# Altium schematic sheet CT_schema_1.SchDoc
size 611 x 441 mm
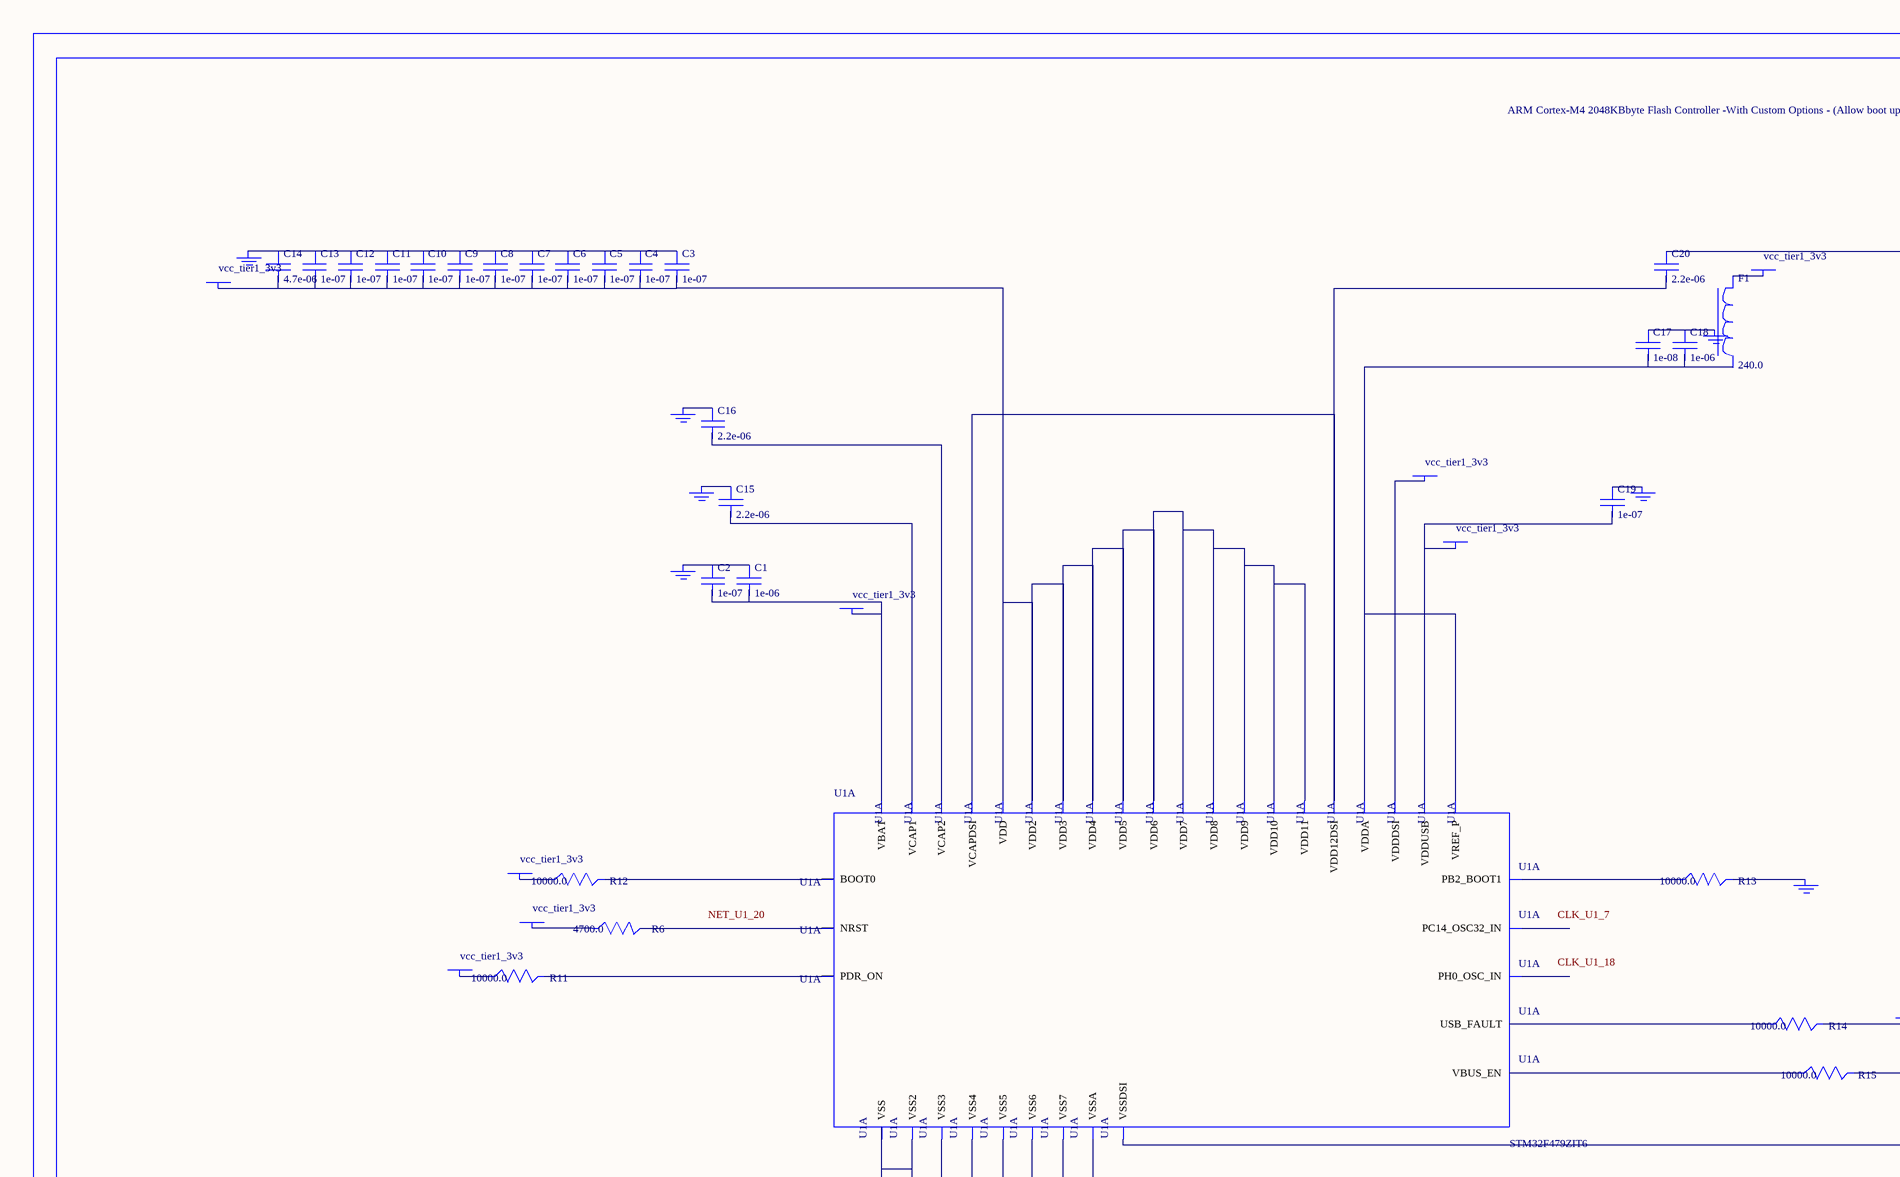
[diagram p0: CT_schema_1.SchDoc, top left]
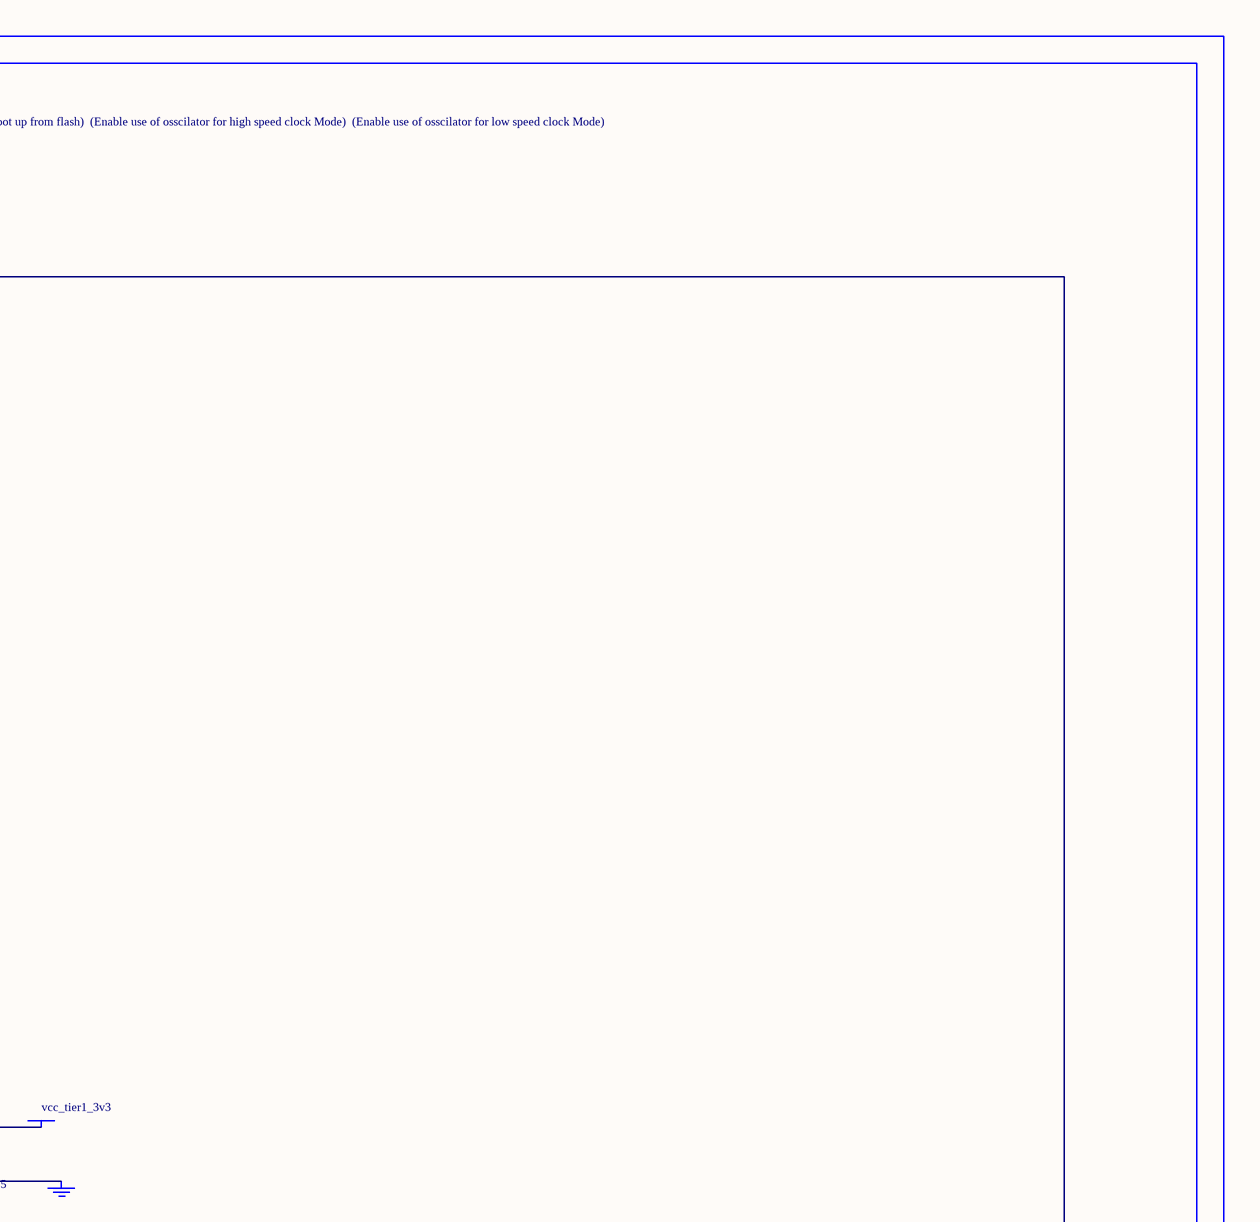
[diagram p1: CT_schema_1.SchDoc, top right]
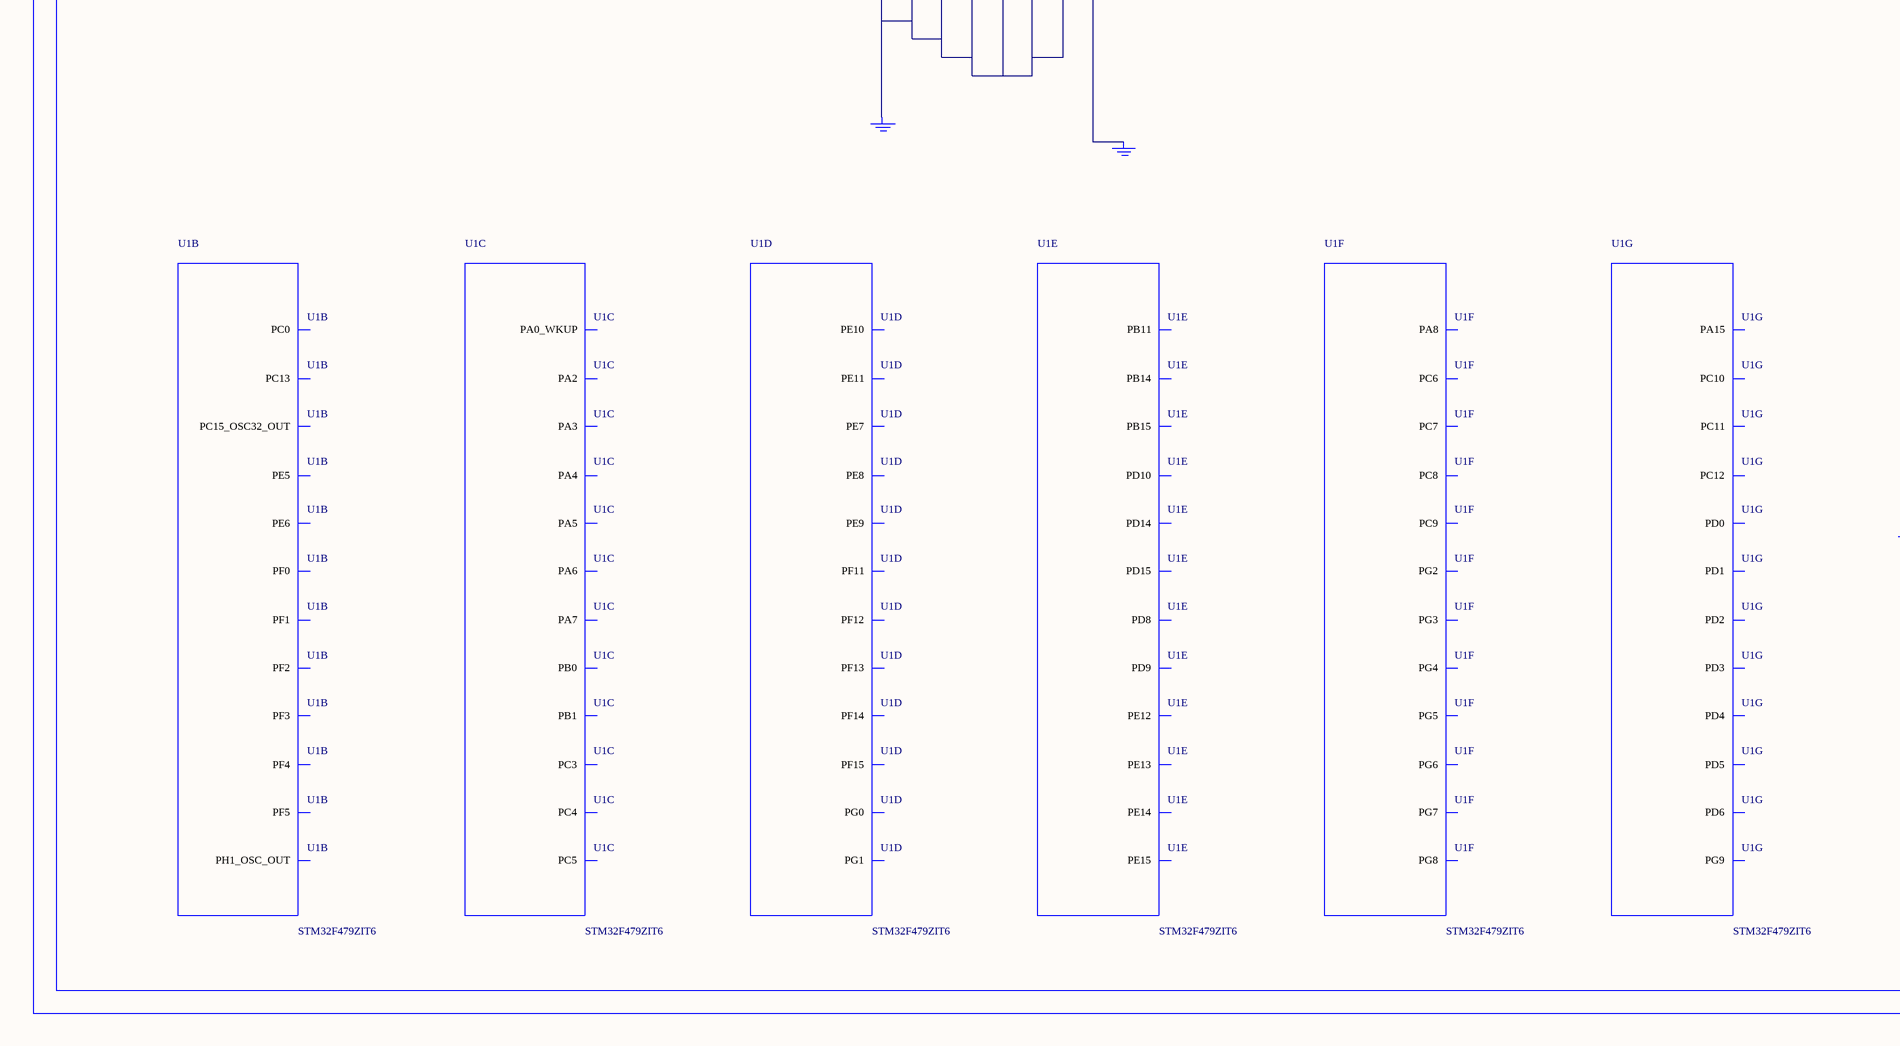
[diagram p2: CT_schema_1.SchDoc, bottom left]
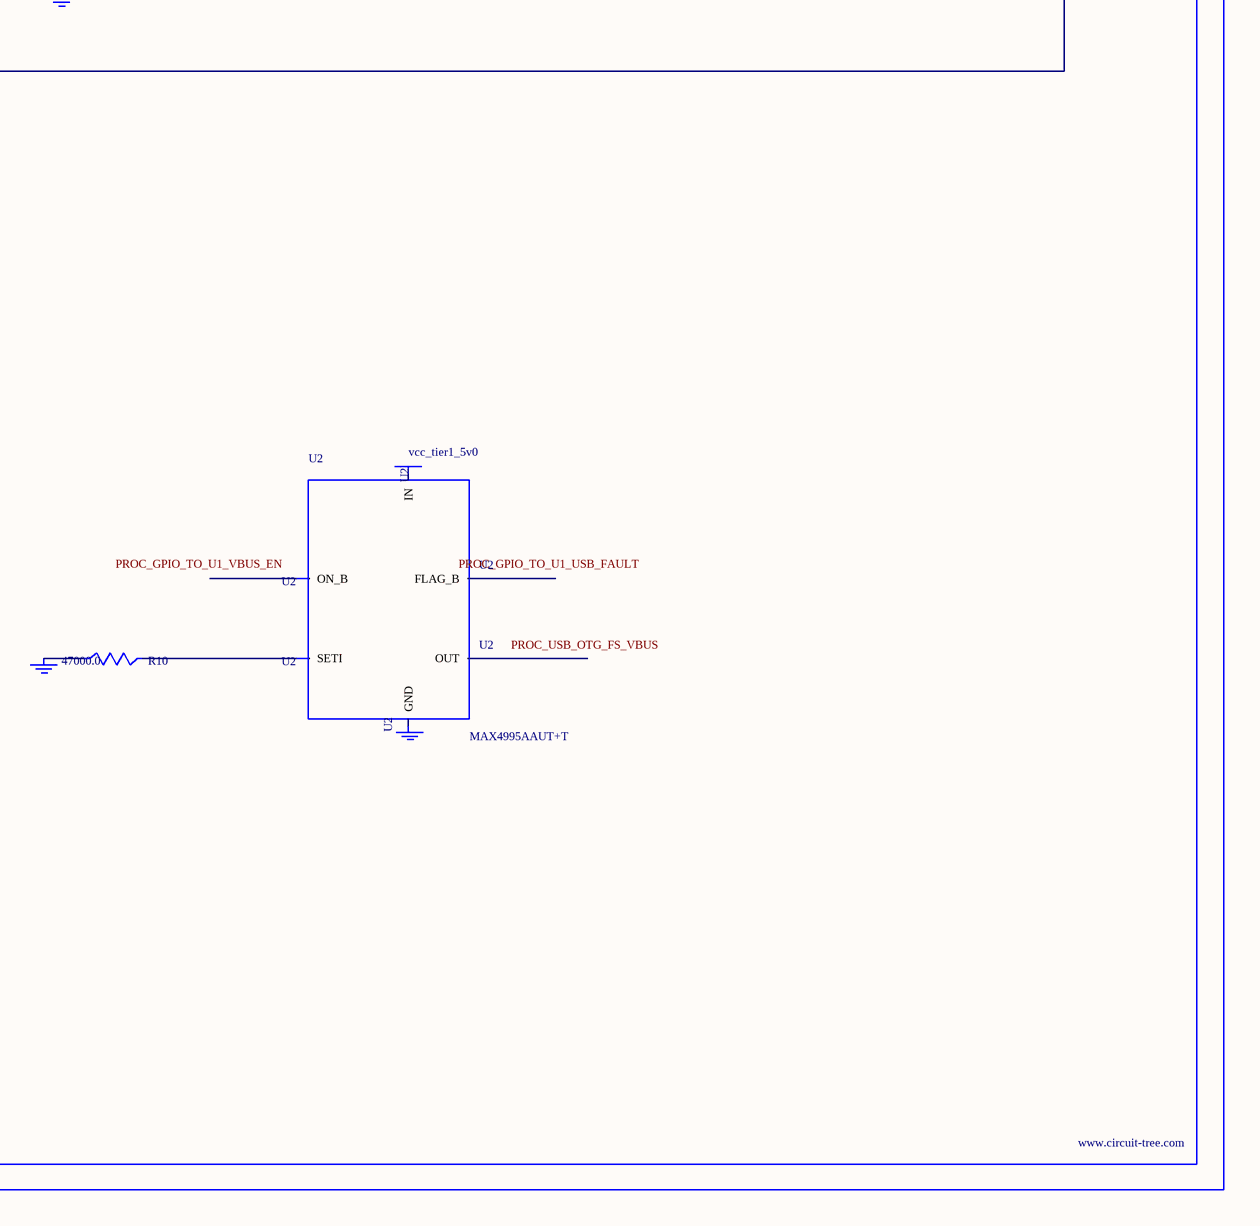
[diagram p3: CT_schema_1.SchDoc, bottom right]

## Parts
BORDER0  (no value)
C1  1e-06  [C0603]
C2  1e-07  [C0603]
C3  1e-07  [C0603]
C4  1e-07  [C0603]
C5  1e-07  [C0603]
C6  1e-07  [C0603]
C7  1e-07  [C0603]
C8  1e-07  [C0603]
C9  1e-07  [C0603]
C10  1e-07  [C0603]
C11  1e-07  [C0603]
C12  1e-07  [C0603]
C13  1e-07  [C0603]
C14  4.7e-06  [C0603]
C15  2.2e-06  [C0603]
C16  2.2e-06  [C0603]
C17  1e-08  [C0603]
C18  1e-06  [C0603]
C19  1e-07  [C0603]
C20  2.2e-06  [C0603]
F1  240.0  [L0603]
GND_INSTANCE_0_0  (no value)
GND_INSTANCE_0_1  (no value)
GND_INSTANCE_0_2  (no value)
GND_INSTANCE_0_3  (no value)
GND_INSTANCE_0_4  (no value)
GND_INSTANCE_0_5  (no value)
GND_INSTANCE_0_6  (no value)
GND_INSTANCE_0_7  (no value)
GND_INSTANCE_0_8  (no value)
GND_INSTANCE_0_9  (no value)
GND_INSTANCE_0_10  (no value)
GND_INSTANCE_0_11  (no value)
POWER_INSTANCE_0_0  vcc_tier1_3v3
POWER_INSTANCE_0_1  vcc_tier1_3v3
POWER_INSTANCE_0_2  vcc_tier1_3v3
POWER_INSTANCE_0_3  vcc_tier1_3v3
POWER_INSTANCE_0_4  vcc_tier1_3v3
POWER_INSTANCE_0_5  vcc_tier1_3v3
POWER_INSTANCE_0_6  vcc_tier1_3v3
POWER_INSTANCE_0_7  vcc_tier1_3v3
POWER_INSTANCE_0_8  vcc_tier1_3v3
POWER_INSTANCE_0_9  vcc_tier1_5v0
R6  4700.0  [R0603]
R10  47000.0  [R0603]
R11  10000.0  [R0603]
R12  10000.0  [R0603]
R13  10000.0  [R0603]
R14  10000.0  [R0603]
R15  10000.0  [R0603]
U1  STM32F479ZIT6  [LQFP144]  (parts A,B,C,D,E,F,G of 13)
U2  MAX4995AAUT+T  [SOT-23-6]

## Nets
NetC1_1: C1.1 C2.1 GND_INSTANCE_0_1.0(GND)
NetC1_2: C1.2 C2.2 POWER_INSTANCE_0_1.0(PWR) U1.5(VBAT)
NetC3_1: C3.1 C4.1 C5.1 C6.1 C7.1 C8.1 C9.1 C10.1 C11.1 C12.1 C13.1 C14.1 GND_INSTANCE_0_2.0(GND)
NetC3_2: C3.2 C4.2 C5.2 C6.2 C7.2 C8.2 C9.2 C10.2 C11.2 C12.2 C13.2 C14.2 POWER_INSTANCE_0_2.0(PWR) U1.16(VDD) U1.25(VDD2) U1.34(VDD3) U1.46(VDD4) U1.56(VDD5) U1.66(VDD6) U1.77(VDD7) U1.110(VDD8) U1.123(VDD9) U1.130(VDD10) U1.143(VDD11)
NetC15_1: C15.1 GND_INSTANCE_0_6.0(GND)
NetC15_2: C15.2 U1.65(VCAP1)
NetC16_1: C16.1 GND_INSTANCE_0_8.0(GND)
NetC16_2: C16.2 U1.108(VCAP2)
NetC17_1: C17.1 C18.1 GND_INSTANCE_0_4.0(GND)
NetC17_2: C17.2 C18.2 U1.27(VREF_P) U1.28(VDDA)
NetC19_1: C19.1 GND_INSTANCE_0_7.0(GND)
NetC19_2: C19.2 POWER_INSTANCE_0_5.0(PWR) U1.97(VDDUSB)
NetC20_1: C20.1 U1.84(VSSDSI)
NetC20_2: C20.2 U1.81(VCAPDSI) U1.87(VDD12DSI)
NetF1_1: F1.1 POWER_INSTANCE_0_3.0(PWR)
NetGND_INSTANCE_0_0_0: GND_INSTANCE_0_0.0(GND) R15.2
NetGND_INSTANCE_0_3_0: GND_INSTANCE_0_3.0(GND) U1.26(VSSA)
NetGND_INSTANCE_0_5_0: GND_INSTANCE_0_5.0(GND) R13.2
NetGND_INSTANCE_0_9_0: GND_INSTANCE_0_9.0(GND) U1.15(VSS) U1.33(VSS2) U1.55(VSS3) U1.76(VSS4) U1.109(VSS5) U1.122(VSS6) U1.129(VSS7)
NetGND_INSTANCE_0_10_0: GND_INSTANCE_0_10.0(GND) R10.1
NetPOWER_INSTANCE_0_0_0: POWER_INSTANCE_0_0.0(PWR) R14.2
NetPOWER_INSTANCE_0_4_0: POWER_INSTANCE_0_4.0(PWR) U1.80(VDDDSI)
NetPOWER_INSTANCE_0_6_0: POWER_INSTANCE_0_6.0(PWR) R12.1
NetPOWER_INSTANCE_0_7_0: POWER_INSTANCE_0_7.0(PWR) R11.1
NetPOWER_INSTANCE_0_8_0: POWER_INSTANCE_0_8.0(PWR) R6.1
NetR6_2: R6.2 U1.20(NRST)
NetR10_2: R10.2 U2.3(SETI)
NetR11_2: R11.2 U1.142(PDR_ON)
NetR12_2: R12.2 U1.137(BOOT0)
NetR13_1: R13.1 U1.43(PB2_BOOT1)
NetR14_1: R14.1 U1.2(USB_FAULT)
NetR15_1: R15.1 U1.1(VBUS_EN)

Not connected (* = marked no-connect by the designer): F1 2; GND_INSTANCE_0_11 0(GND); POWER_INSTANCE_0_9 0(PWR); U1 3(PE5) 4(PE6) 6(PC13) 7(PC14_OSC32_IN) 8(PC15_OSC32_OUT) 9(PF0) 10(PF1) 11(PF2) 12(PF3) 13(PF4) 14(PF5) 18(PH0_OSC_IN) 19(PH1_OSC_OUT) 21(PC0) 24(PC3) 29(PA0_WKUP) 31(PA2) 32(PA3) 35(PA4) 36(PA5) 37(PA6) 38(PA7) 39(PC4) 40(PC5) 41(PB0) 42(PB1) 44(PF11) 45(PF12) 47(PF13) 48(PF14) 49(PF15) 50(PG0) 51(PG1) 52(PE7) 53(PE8) 54(PE9) 57(PE10) 58(PE11) 59(PE12) 60(PE13) 61(PE14) 62(PE15) 64(PB11) 69(PB14) 70(PB15) 71(PD8) 72(PD9) 73(PD10) 78(PD14) 79(PD15) 90(PG2) 91(PG3) 92(PG4) 93(PG5) 94(PG6) 95(PG7) 96(PG8) 98(PC6) 99(PC7) 100(PC8) 101(PC9) 102(PA8) 112(PA15) 113(PC10) 114(PC11) 115(PC12) 116(PD0) 117(PD1) 118(PD2) 119(PD3) 120(PD4) 121(PD5) 124(PD6) 125(PG9); U2 1(OUT) 2(GND) 4(ON_B) 5(IN) 6(FLAG_B)

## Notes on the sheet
- Labels drawn without touching a wire or pin: CLK_U1_7, CLK_U1_18, NET_U1_20, PROC_GPIO_TO_U1_USB_FAULT, PROC_GPIO_TO_U1_VBUS_EN, PROC_USB_OTG_FS_VBUS

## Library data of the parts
BORDER0 = BORDER_PAGE0
C1 C18 = C0603C105K3RACTU
C2-C13 C19 = 06035C104K4Z2A
C14 = GRM188R6YA475KE15D
C15 C16 C20 = C0603C225K8RACTU
C17 = 06035C103K4Z2A
F1 = Z0603C241ASMST
GND_INSTANCE_0_0-GND_INSTANCE_0_11 = GND
POWER_INSTANCE_0_0-POWER_INSTANCE_0_9 = PWR
R6 = RC0603JR-074K7L
R10 = RC0603JR-0747KL
R11-R15 = RC0603JR-0710KL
